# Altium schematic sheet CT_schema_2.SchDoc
size 539 x 398 mm
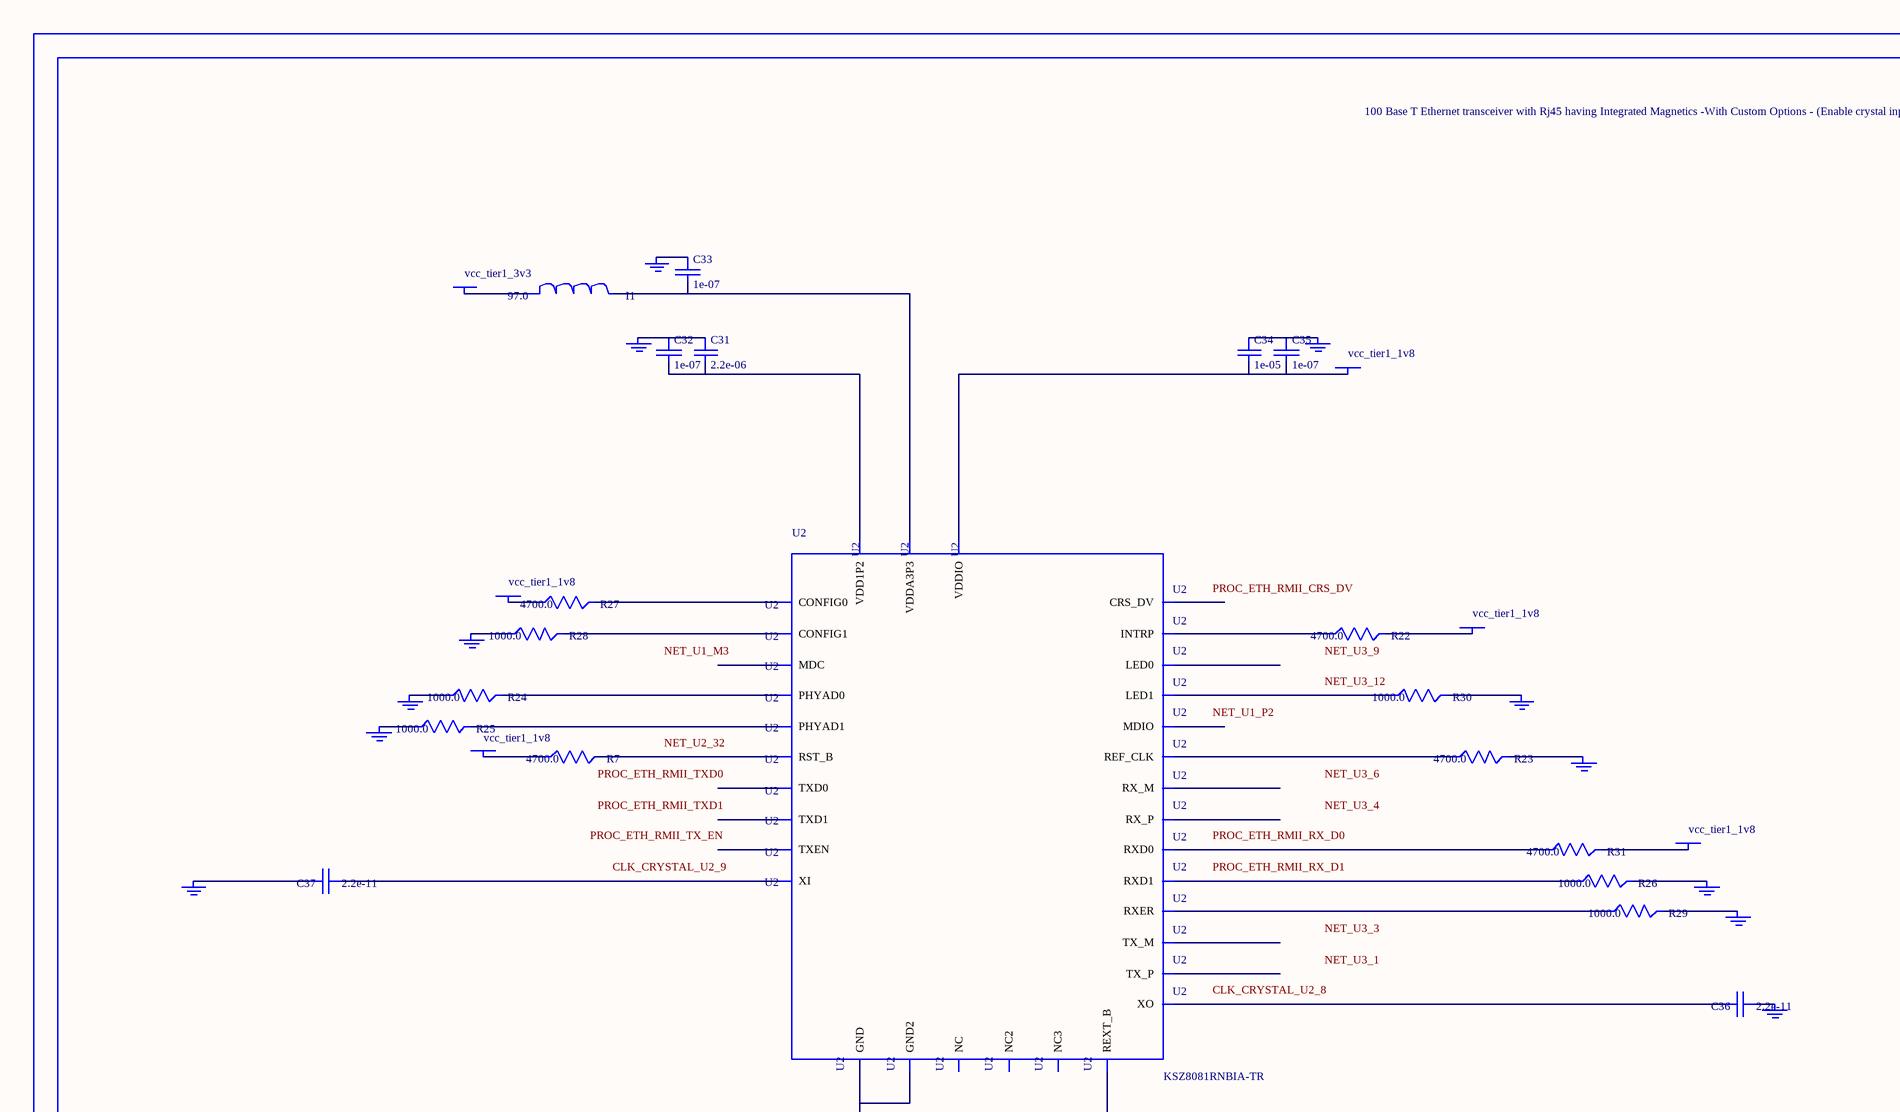
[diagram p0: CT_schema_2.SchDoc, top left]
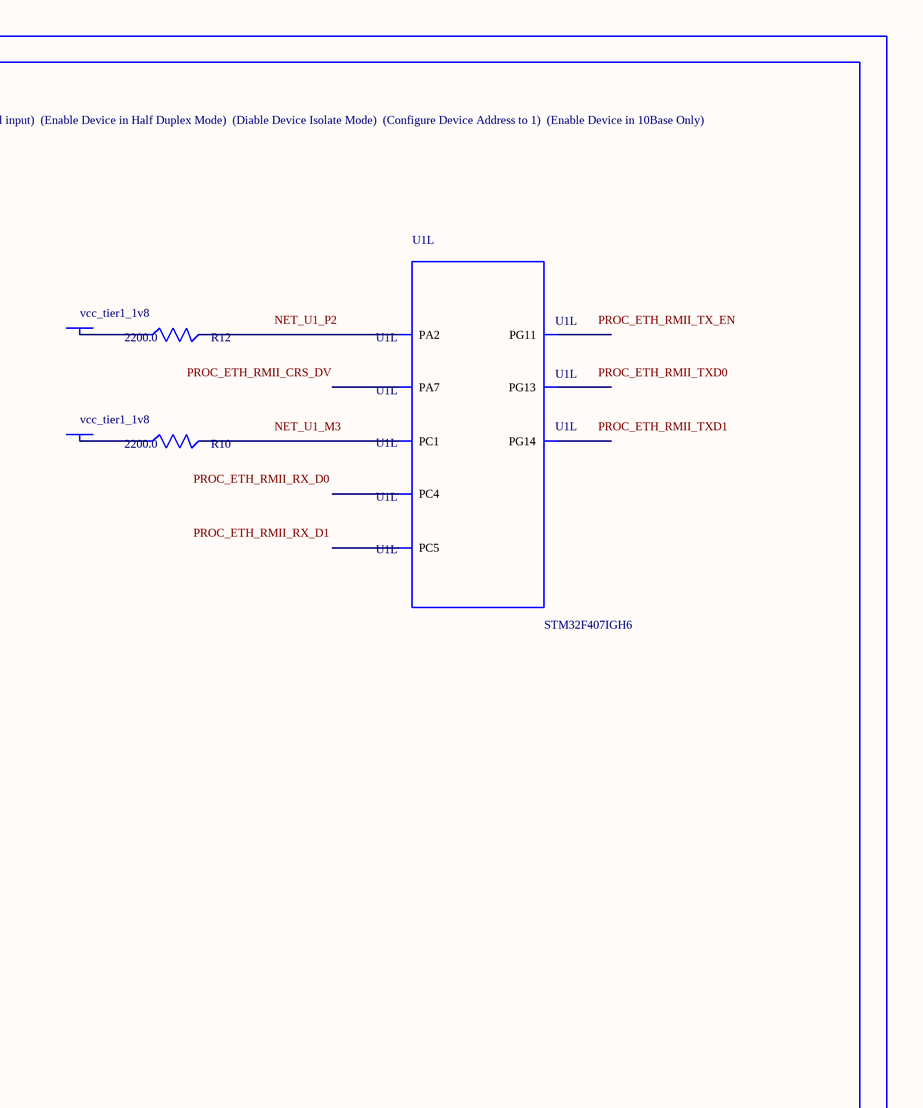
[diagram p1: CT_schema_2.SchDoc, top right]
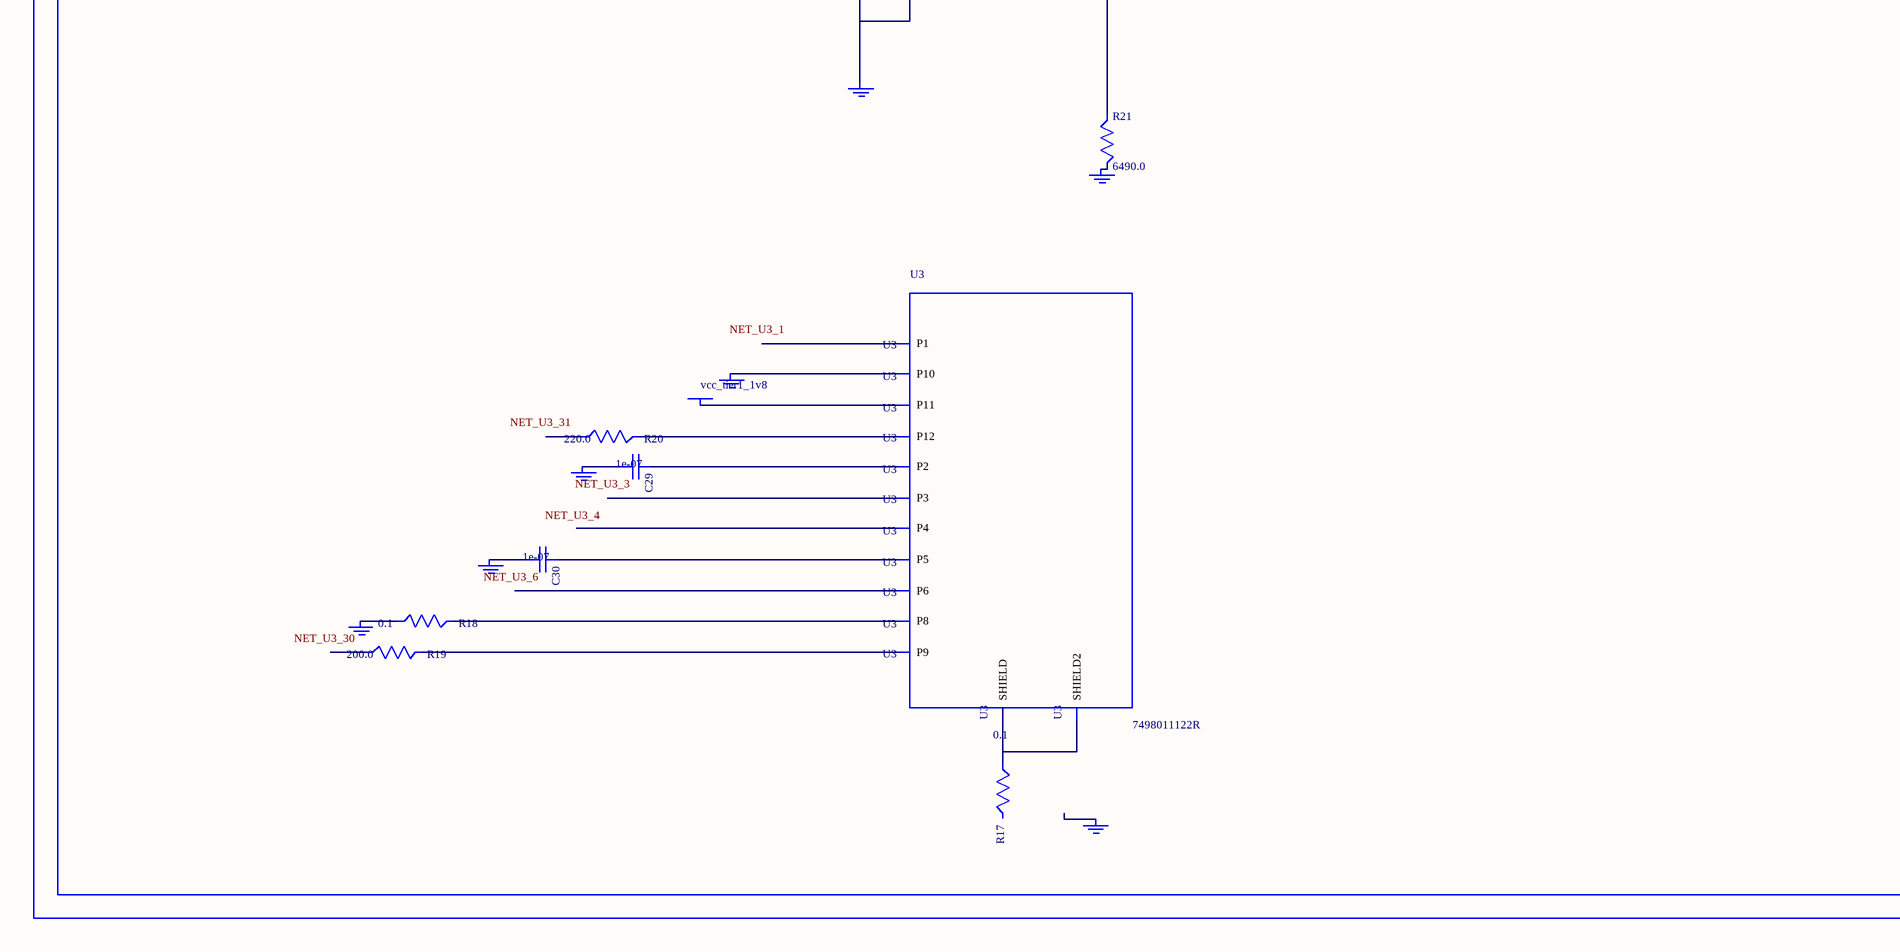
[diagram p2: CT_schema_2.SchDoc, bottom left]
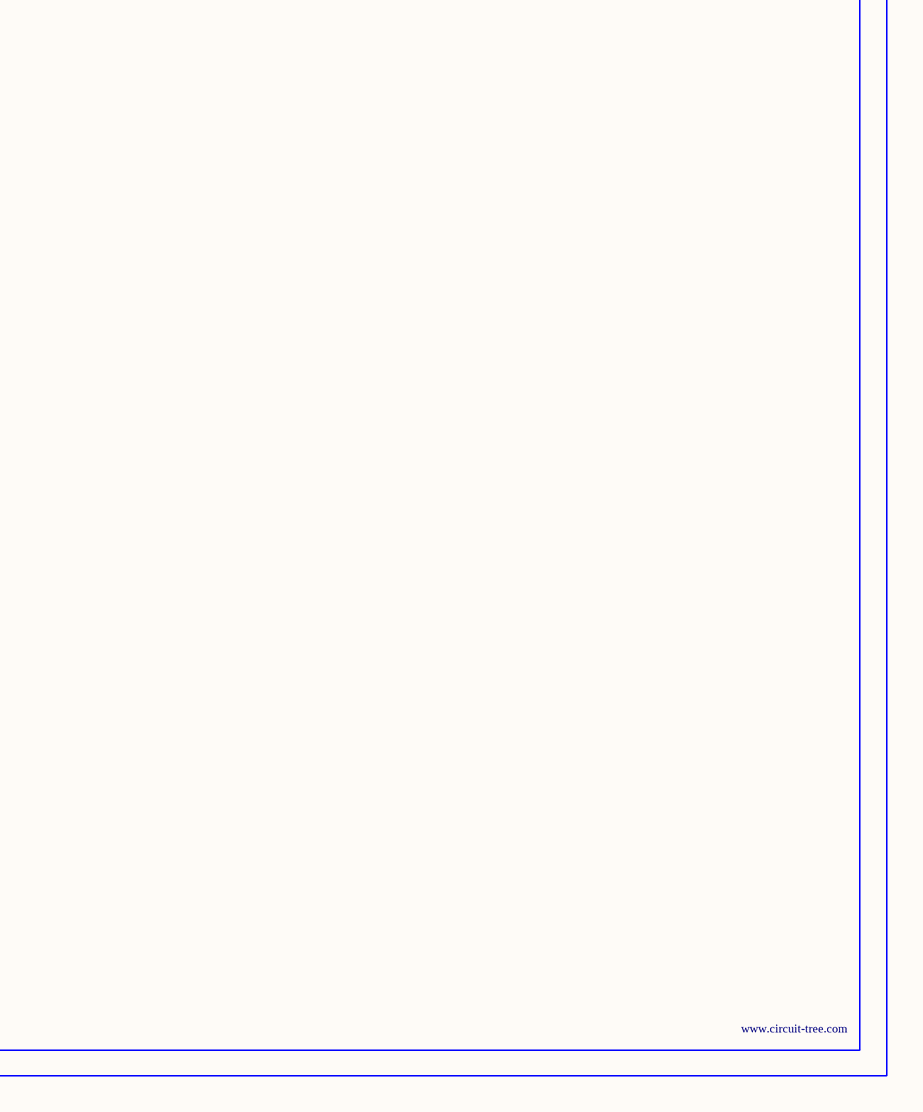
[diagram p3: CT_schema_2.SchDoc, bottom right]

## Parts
BORDER1  (no value)
C29  1e-07  [C0402]
C30  1e-07  [C0402]
C31  2.2e-06  [C0603]
C32  1e-07  [C0402]
C33  1e-07  [C0402]
C34  1e-05  [C0805]
C35  1e-07  [C0402]
C36  2.2e-11  [C0402]
C37  2.2e-11  [C0402]
GND_INSTANCE_1_0  (no value)
GND_INSTANCE_1_1  (no value)
GND_INSTANCE_1_2  (no value)
GND_INSTANCE_1_3  (no value)
GND_INSTANCE_1_4  (no value)
GND_INSTANCE_1_5  (no value)
GND_INSTANCE_1_6  (no value)
GND_INSTANCE_1_7  (no value)
GND_INSTANCE_1_8  (no value)
GND_INSTANCE_1_9  (no value)
GND_INSTANCE_1_10  (no value)
GND_INSTANCE_1_11  (no value)
GND_INSTANCE_1_12  (no value)
GND_INSTANCE_1_13  (no value)
GND_INSTANCE_1_14  (no value)
GND_INSTANCE_1_15  (no value)
GND_INSTANCE_1_16  (no value)
GND_INSTANCE_1_17  (no value)
GND_INSTANCE_1_18  (no value)
I1  97.0  [R0603]
POWER_INSTANCE_1_0  vcc_tier1_3v3
POWER_INSTANCE_1_1  vcc_tier1_1v8
POWER_INSTANCE_1_2  vcc_tier1_1v8
POWER_INSTANCE_1_3  vcc_tier1_1v8
POWER_INSTANCE_1_4  vcc_tier1_1v8
POWER_INSTANCE_1_5  vcc_tier1_1v8
POWER_INSTANCE_1_6  vcc_tier1_1v8
POWER_INSTANCE_1_7  vcc_tier1_1v8
POWER_INSTANCE_1_8  vcc_tier1_1v8
R7  4700.0  [R0603]
R10  2200.0  [R0603]
R12  2200.0  [R0603]
R17  0.1  [R0603]
R18  0.1  [R0603]
R19  200.0  [R0603]
R20  220.0  [R0603]
R21  6490.0  [R0603]
R22  4700.0  [R0603]
R23  4700.0  [R0603]
R24  1000.0  [R0603]
R25  1000.0  [R0603]
R26  1000.0  [R0603]
R27  4700.0  [R0603]
R28  1000.0  [R0603]
R29  1000.0  [R0603]
R30  1000.0  [R0603]
R31  4700.0  [R0603]
U1  STM32F407IGH6  [UFBGA176]  (part L of 15)
U2  KSZ8081RNBIA-TR  [QFN-32]
U3  7498011122R  [7498011122R]

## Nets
NetC29_1: C29.1 U3.2(P2)
NetC29_2: C29.2 GND_INSTANCE_1_14.0(GND)
NetC30_1: C30.1 U3.5(P5)
NetC30_2: C30.2 GND_INSTANCE_1_15.0(GND)
NetC31_1: C31.1 C32.1 GND_INSTANCE_1_0.0(GND)
NetC31_2: C31.2 C32.2 U2.2(VDD1P2)
NetC33_1: C33.1 GND_INSTANCE_1_1.0(GND)
NetC33_2: C33.2 I1.2 U2.3(VDDA3P3)
NetC34_1: C34.1 C35.1 GND_INSTANCE_1_8.0(GND)
NetC34_2: C34.2 C35.2 POWER_INSTANCE_1_2.0(PWR) U2.17(VDDIO)
NetC36_1: C36.1 GND_INSTANCE_1_2.0(GND)
NetC36_2: C36.2 U2.8(XO)
NetC37_1: C37.1 U2.9(XI)
NetC37_2: C37.2 GND_INSTANCE_1_3.0(GND)
NetGND_INSTANCE_1_4_0: GND_INSTANCE_1_4.0(GND) R21.2
NetGND_INSTANCE_1_5_0: GND_INSTANCE_1_5.0(GND) R24.1
NetGND_INSTANCE_1_6_0: GND_INSTANCE_1_6.0(GND) R25.1
NetGND_INSTANCE_1_7_0: GND_INSTANCE_1_7.0(GND) R26.2
NetGND_INSTANCE_1_9_0: GND_INSTANCE_1_9.0(GND) R23.2
NetGND_INSTANCE_1_10_0: GND_INSTANCE_1_10.0(GND) R29.2
NetGND_INSTANCE_1_11_0: GND_INSTANCE_1_11.0(GND) R28.1
NetGND_INSTANCE_1_12_0: GND_INSTANCE_1_12.0(GND) R30.2
NetGND_INSTANCE_1_13_0: GND_INSTANCE_1_13.0(GND) U2.1(GND) U2.EXP(GND2)
NetGND_INSTANCE_1_16_0: GND_INSTANCE_1_16.0(GND) R18.1
NetGND_INSTANCE_1_17_0: GND_INSTANCE_1_17.0(GND) U3.10(P10)
NetI1_1: I1.1 POWER_INSTANCE_1_0.0(PWR)
NetPOWER_INSTANCE_1_1_0: POWER_INSTANCE_1_1.0(PWR) R31.2
NetPOWER_INSTANCE_1_3_0: POWER_INSTANCE_1_3.0(PWR) R22.2
NetPOWER_INSTANCE_1_4_0: POWER_INSTANCE_1_4.0(PWR) R27.1
NetPOWER_INSTANCE_1_5_0: POWER_INSTANCE_1_5.0(PWR) R7.1
NetPOWER_INSTANCE_1_6_0: POWER_INSTANCE_1_6.0(PWR) R12.1
NetPOWER_INSTANCE_1_7_0: POWER_INSTANCE_1_7.0(PWR) R10.1
NetPOWER_INSTANCE_1_8_0: POWER_INSTANCE_1_8.0(PWR) U3.11(P11)
NetR7_2: R7.2 U2.32(RST_B)
NetR10_2: R10.2 U1.M3(PC1)
NetR12_2: R12.2 U1.P2(PA2)
NetR17_1: R17.1 U3.13(SHIELD) U3.14(SHIELD2)
NetR18_2: R18.2 U3.8(P8)
NetR19_2: R19.2 U3.9(P9)
NetR20_2: R20.2 U3.12(P12)
NetR21_1: R21.1 U2.10(REXT_B)
NetR22_1: R22.1 U2.21(INTRP)
NetR23_1: R23.1 U2.19(REF_CLK)
NetR24_2: R24.2 U2.13(PHYAD0)
NetR25_2: R25.2 U2.14(PHYAD1)
NetR26_1: R26.1 U2.15(RXD1)
NetR27_2: R27.2 U2.28(CONFIG0)
NetR28_2: R28.2 U2.29(CONFIG1)
NetR29_1: R29.1 U2.20(RXER)
NetR30_1: R30.1 U2.31(LED1)
NetR31_1: R31.1 U2.16(RXD0)

Not connected (* = marked no-connect by the designer): GND_INSTANCE_1_18 0(GND); R17 2; R19 1; R20 1; U1 A7(PG14) A8(PG13) B9(PG11) N5(PC4) P5(PC5) R3(PA7); U2 4(RX_M) 5(RX_P) 6(TX_M) 7(TX_P) 11(MDIO) 12(MDC) 18(CRS_DV) 22(NC) 23(TXEN) 24(TXD0) 25(TXD1) 26(NC2) 27(NC3) 30(LED0); U3 1(P1) 3(P3) 4(P4) 6(P6)

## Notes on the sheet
- Labels drawn without touching a wire or pin: CLK_CRYSTAL_U2_8, CLK_CRYSTAL_U2_9, NET_U1_M3, NET_U1_P2, NET_U2_32, NET_U3_1, NET_U3_3, NET_U3_4, NET_U3_6, NET_U3_9, NET_U3_12, NET_U3_30, NET_U3_31, PROC_ETH_RMII_CRS_DV, PROC_ETH_RMII_RX_D0, PROC_ETH_RMII_RX_D1, PROC_ETH_RMII_TX_EN, PROC_ETH_RMII_TXD0, PROC_ETH_RMII_TXD1

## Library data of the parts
BORDER1 = BORDER_PAGE1
C29 C30 C32 C33 C35 = C0402C104K3RACTU
C31 = C0603C225K8RACTU
C34 = C0805C106K8RACTU
C36 C37 = C0402C220K3RAC
GND_INSTANCE_1_0-GND_INSTANCE_1_18 = GND
I1 = I1
POWER_INSTANCE_1_0-POWER_INSTANCE_1_8 = PWR
R7 R22 R23 R27 R31 = RC0603JR-074K7L
R10 R12 = RC0603JR-072K2L
R17 R18 = ERJ-3RSFR10V
R19 = RC0603JR-07200RL
R20 = RC0603JR-07220RL
R21 = ERJ-3EKF6491V
R24-R26 R28-R30 = RC0603JR-071KL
